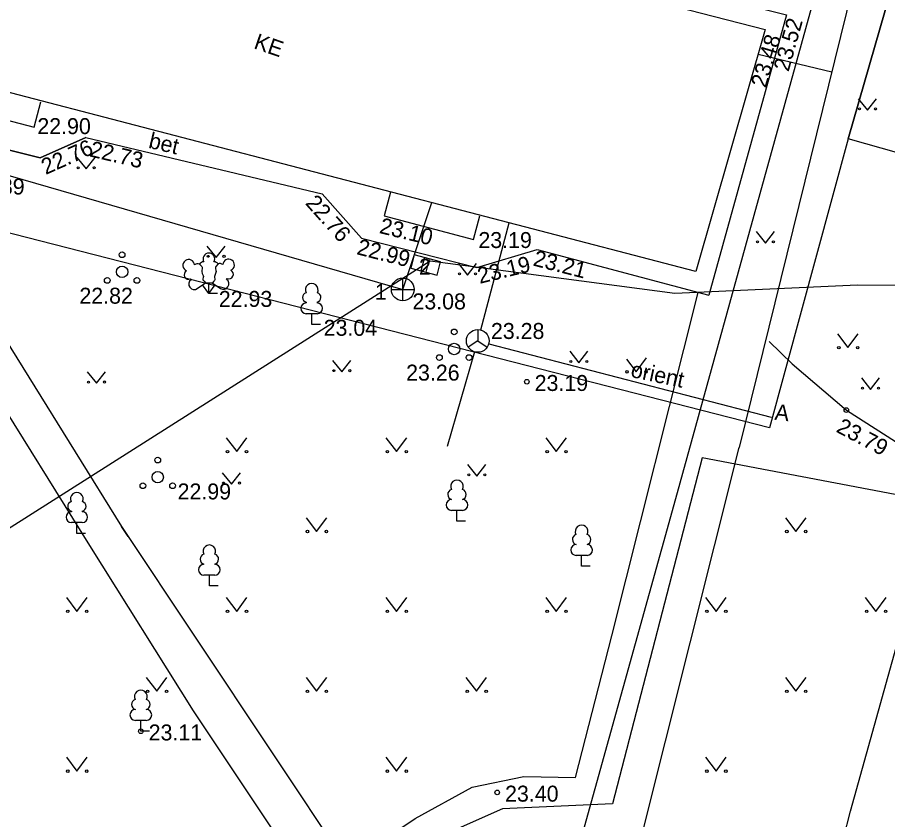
# Model space of a CAD drawing. Extents: x 714391 to 714584, y 6589993 to 6590151.
# Drawn here: x 714490.89 to 714529.01, y 6590039.38 to 6590074.53 of the extents above; entities that cross this region are included whole.
import ezdxf

# ---------------------------------------------------------------- set-up
doc = ezdxf.new("R2010")
doc.units = 0
for name, color, linetype in [('HALJASTUS', 7, 'Continuous'), ('HOONE', 7, 'Continuous'), ('HOONEDET', 7, 'Continuous'), ('KKAEV', 7, 'Continuous'), ('KORGUS', 7, 'Continuous'), ('KTRASS', 7, 'Continuous'), ('MPKAABEL', 7, 'Continuous'), ('POST', 7, 'Continuous'), ('PUU', 7, 'Continuous'), ('SIKAEV', 7, 'Continuous'), ('SITRASS', 7, 'Continuous'), ('SKTRASS', 7, 'Continuous'), ('TEE', 7, 'Continuous'), ('TORU NR', 7, 'Continuous'), ('TTRASS', 7, 'Continuous'), ('По умолчанию', 7, 'Continuous'), ('Слой 1', 7, 'Continuous')]:
    doc.layers.add(name, color=color, linetype=linetype)

msp = doc.modelspace()

# ---------------------------------------------------------------- linework, layer by layer
at = {"layer": 'HALJASTUS'}
for p, q in [((714527.73, 6590070.967), (714528.135, 6590070.462)), ((714528.135, 6590070.462), (714528.53, 6590070.967)), ((714493.503, 6590068.393), (714493.908, 6590067.888)), ((714493.908, 6590067.888), (714494.303, 6590068.393)), ((714523.259, 6590065.142), (714523.664, 6590064.637)), ((714523.664, 6590064.637), (714524.059, 6590065.142)), ((714499.193, 6590064.51), (714499.598, 6590064.005)), ((714499.598, 6590064.005), (714499.993, 6590064.51)), ((714510.21, 6590063.742), (714510.615, 6590063.237)), ((714510.615, 6590063.237), (714511.01, 6590063.742)), ((714526.815, 6590060.664), (714527.278, 6590060.057)), ((714527.278, 6590060.057), (714527.724, 6590060.664)), ((714515.087, 6590059.904), (714515.492, 6590059.399)), ((714515.492, 6590059.399), (714515.887, 6590059.904)), ((714504.701, 6590059.498), (714505.106, 6590058.993)), ((714505.106, 6590058.993), (714505.501, 6590059.498)), ((714493.955, 6590059.001), (714494.36, 6590058.496)), ((714494.36, 6590058.496), (714494.755, 6590059.001)), ((714527.865, 6590058.73), (714528.27, 6590058.225)), ((714528.27, 6590058.225), (714528.665, 6590058.73)), ((714500.037, 6590056.107), (714500.5, 6590055.5)), ((714500.5, 6590055.5), (714500.946, 6590056.107)), ((714507.037, 6590056.107), (714507.5, 6590055.5)), ((714507.5, 6590055.5), (714507.946, 6590056.107)), ((714514.037, 6590056.107), (714514.5, 6590055.5)), ((714514.5, 6590055.5), (714514.946, 6590056.107)), ((714510.616, 6590054.937), (714511.021, 6590054.432)), ((714511.021, 6590054.432), (714511.416, 6590054.937)), ((714499.87, 6590054.576), (714500.275, 6590054.071)), ((714500.275, 6590054.071), (714500.67, 6590054.576)), ((714503.537, 6590052.607), (714504, 6590052)), ((714504, 6590052), (714504.446, 6590052.607)), ((714524.537, 6590052.607), (714525, 6590052)), ((714525, 6590052), (714525.446, 6590052.607)), ((714493.037, 6590049.107), (714493.5, 6590048.5)), ((714493.5, 6590048.5), (714493.946, 6590049.107)), ((714500.037, 6590049.107), (714500.5, 6590048.5)), ((714500.5, 6590048.5), (714500.946, 6590049.107)), ((714507.037, 6590049.107), (714507.5, 6590048.5)), ((714507.5, 6590048.5), (714507.946, 6590049.107)), ((714514.037, 6590049.107), (714514.5, 6590048.5)), ((714514.5, 6590048.5), (714514.946, 6590049.107)), ((714521.037, 6590049.107), (714521.5, 6590048.5)), ((714521.5, 6590048.5), (714521.946, 6590049.107)), ((714528.037, 6590049.107), (714528.5, 6590048.5)), ((714528.5, 6590048.5), (714528.946, 6590049.107)), ((714496.537, 6590045.607), (714497, 6590045)), ((714497, 6590045), (714497.446, 6590045.607)), ((714503.537, 6590045.607), (714504, 6590045)), ((714504, 6590045), (714504.446, 6590045.607)), ((714510.537, 6590045.607), (714511, 6590045)), ((714511, 6590045), (714511.446, 6590045.607)), ((714524.537, 6590045.607), (714525, 6590045)), ((714525, 6590045), (714525.446, 6590045.607)), ((714493.037, 6590042.107), (714493.5, 6590041.5)), ((714493.5, 6590041.5), (714493.946, 6590042.107)), ((714507.037, 6590042.107), (714507.5, 6590041.5)), ((714507.5, 6590041.5), (714507.946, 6590042.107)), ((714521.037, 6590042.107), (714521.5, 6590041.5)), ((714521.5, 6590041.5), (714521.946, 6590042.107))]:
    msp.add_line(p, q, dxfattribs=at)
for centre, radius in [((714527.782, 6590070.517), 0.0428), ((714528.482, 6590070.517), 0.0452), ((714493.555, 6590067.943), 0.0428), ((714494.255, 6590067.943), 0.0452), ((714523.311, 6590064.692), 0.0428), ((714524.011, 6590064.692), 0.0452), ((714495.479, 6590064.13), 0.125), ((714499.245, 6590064.06), 0.0428), ((714499.945, 6590064.06), 0.0452), ((714495.479, 6590063.38), 0.25), ((714494.829, 6590063.005), 0.125), ((714496.129, 6590063.005), 0.125), ((714510.262, 6590063.292), 0.0428), ((714510.962, 6590063.292), 0.0452), ((714510.029, 6590060.747), 0.125), ((714510.029, 6590059.997), 0.25), ((714526.877, 6590060.057), 0.055), ((714527.706, 6590060.057), 0.055), ((714509.379, 6590059.622), 0.125), ((714510.679, 6590059.622), 0.125), ((714515.139, 6590059.454), 0.0428), ((714515.839, 6590059.454), 0.0452), ((714504.753, 6590059.048), 0.0428), ((714505.453, 6590059.048), 0.0452), ((714494.007, 6590058.551), 0.0428), ((714494.707, 6590058.551), 0.0452), ((714527.917, 6590058.28), 0.0428), ((714528.617, 6590058.28), 0.0452), ((714500.099, 6590055.5), 0.055), ((714500.928, 6590055.5), 0.055), ((714507.099, 6590055.5), 0.055), ((714507.928, 6590055.5), 0.055), ((714514.099, 6590055.5), 0.055), ((714514.928, 6590055.5), 0.055), ((714497.04, 6590055.131), 0.125), ((714497.04, 6590054.381), 0.25), ((714510.668, 6590054.488), 0.0428), ((714511.368, 6590054.488), 0.0452), ((714496.39, 6590054.006), 0.125), ((714497.69, 6590054.006), 0.125), ((714499.922, 6590054.126), 0.0428), ((714500.622, 6590054.126), 0.0452), ((714503.599, 6590052), 0.055), ((714504.428, 6590052), 0.055), ((714524.599, 6590052), 0.055), ((714525.428, 6590052), 0.055), ((714493.099, 6590048.5), 0.055), ((714493.928, 6590048.5), 0.055), ((714500.099, 6590048.5), 0.055), ((714500.928, 6590048.5), 0.055), ((714507.099, 6590048.5), 0.055), ((714507.928, 6590048.5), 0.055), ((714514.099, 6590048.5), 0.055), ((714514.928, 6590048.5), 0.055), ((714521.099, 6590048.5), 0.055), ((714521.928, 6590048.5), 0.055), ((714528.099, 6590048.5), 0.055), ((714528.928, 6590048.5), 0.055), ((714496.599, 6590045), 0.055), ((714497.428, 6590045), 0.055), ((714503.599, 6590045), 0.055), ((714504.428, 6590045), 0.055), ((714510.599, 6590045), 0.055), ((714511.428, 6590045), 0.055), ((714524.599, 6590045), 0.055), ((714525.428, 6590045), 0.055), ((714493.099, 6590041.5), 0.055), ((714493.928, 6590041.5), 0.055), ((714507.099, 6590041.5), 0.055), ((714507.928, 6590041.5), 0.055), ((714521.099, 6590041.5), 0.055), ((714521.928, 6590041.5), 0.055)]:
    msp.add_circle(centre, radius, dxfattribs=at)
at = {"layer": 'HOONE'}
for points in [[(714520.618, 6590063.399), (714481.385, 6590073.617), (714484.074, 6590084.17), (714523.648, 6590073.994), (714520.618, 6590063.399)], [(714487.937, 6590071.893), (714487.647, 6590070.755), (714491.627, 6590069.716), (714491.916, 6590070.835)], [(714507.236, 6590066.871), (714506.966, 6590065.84), (714510.869, 6590064.791), (714511.151, 6590065.835)]]:
    msp.add_lwpolyline(points, dxfattribs=at)
at = {"layer": 'KKAEV'}
for p, q in [((714507.775, 6590062.109), (714507.775, 6590063.109)), ((714507.275, 6590062.609), (714508.275, 6590062.609))]:
    msp.add_line(p, q, dxfattribs=at)
msp.add_circle((714507.775, 6590062.609), 0.5, dxfattribs=at)
at = {"layer": 'KORGUS'}
for centre in [(714513.21, 6590058.564), (714527.207, 6590057.322), (714496.3, 6590043.248), (714511.913, 6590040.568)]:
    msp.add_circle(centre, 0.1, dxfattribs=at)
at = {"layer": 'KTRASS'}
for p, q in [((714488.663, 6590068.145), (714507.775, 6590062.609)), ((714507.775, 6590062.609), (714509.052, 6590066.411))]:
    msp.add_line(p, q, dxfattribs=at)
at = {"layer": 'MPKAABEL'}
msp.add_lwpolyline([(714558.719, 6590063.793), (714557.614, 6590062.993), (714553.32, 6590062.662), (714527.694, 6590062.802), (714519.691, 6590062.433), (714508.979, 6590063.853), (714473.93, 6590041.599)], dxfattribs=at)
at = {"layer": 'POST'}
for p, q in [((714508.281, 6590064.124), (714508.127, 6590063.547)), ((714509.435, 6590063.816), (714508.281, 6590064.124)), ((714508.727, 6590064.005), (714508.573, 6590063.428)), ((714508.937, 6590063.949), (714508.783, 6590063.372)), ((714508.127, 6590063.547), (714509.282, 6590063.24)), ((714509.282, 6590063.24), (714509.435, 6590063.816))]:
    msp.add_line(p, q, dxfattribs=at)
at = {"layer": 'PUU'}
for p, q in [((714498.498, 6590063.031), (714498.473, 6590063.066)), ((714498.773, 6590062.646), (714499.133, 6590062.901)), ((714499.283, 6590062.426), (714499.008, 6590062.811)), ((714499.133, 6590062.901), (714499.428, 6590062.901)), ((714499.283, 6590062.426), (714499.283, 6590062.901)), ((714499.283, 6590062.426), (714499.553, 6590062.816)), ((714499.428, 6590062.901), (714499.788, 6590062.656)), ((714500.058, 6590063.046), (714500.078, 6590063.081)), ((714499.663, 6590062.426), (714499.283, 6590062.426)), ((714503.547, 6590062.049), (714503.547, 6590062.019)), ((714504.027, 6590062.049), (714504.027, 6590062.019)), ((714504.027, 6590061.544), (714503.547, 6590061.544)), ((714503.787, 6590061.069), (714503.787, 6590061.544)), ((714504.167, 6590061.069), (714503.787, 6590061.069)), ((714493.257, 6590052.896), (714493.257, 6590052.866)), ((714493.737, 6590052.896), (714493.737, 6590052.866)), ((714510.389, 6590052.926), (714509.909, 6590052.926)), ((714510.149, 6590052.451), (714510.149, 6590052.926)), ((714510.529, 6590052.451), (714510.149, 6590052.451)), ((714493.737, 6590052.391), (714493.257, 6590052.391)), ((714493.497, 6590051.916), (714493.497, 6590052.391)), ((714493.877, 6590051.916), (714493.497, 6590051.916)), ((714515.849, 6590050.954), (714515.369, 6590050.954)), ((714515.609, 6590050.479), (714515.609, 6590050.954)), ((714515.989, 6590050.479), (714515.609, 6590050.479)), ((714499.543, 6590050.088), (714499.063, 6590050.088)), ((714499.303, 6590049.613), (714499.303, 6590050.088)), ((714499.683, 6590049.613), (714499.303, 6590049.613)), ((714496.54, 6590043.723), (714496.06, 6590043.723)), ((714496.3, 6590043.248), (714496.3, 6590043.723)), ((714496.68, 6590043.248), (714496.3, 6590043.248))]:
    msp.add_line(p, q, dxfattribs=at)
for points in [[(714498.868, 6590063.711), (714498.973, 6590063.611), (714498.988, 6590063.581), (714498.988, 6590063.526), (714498.973, 6590063.436), (714498.973, 6590063.391), (714498.993, 6590063.311), (714499.033, 6590063.221), (714499.043, 6590063.176), (714499.038, 6590063.131), (714499.023, 6590063.066), (714499.023, 6590063.036), (714499.043, 6590062.996), (714499.068, 6590062.966), (714499.133, 6590062.901)], [(714499.688, 6590063.726), (714499.593, 6590063.611), (714499.578, 6590063.581), (714499.578, 6590063.526), (714499.593, 6590063.436), (714499.598, 6590063.391), (714499.578, 6590063.311), (714499.538, 6590063.221), (714499.528, 6590063.176), (714499.533, 6590063.131), (714499.548, 6590063.066), (714499.548, 6590063.036), (714499.528, 6590062.996), (714499.503, 6590062.966), (714499.433, 6590062.901)]]:
    msp.add_lwpolyline(points, dxfattribs=at)
for centre, radius, start, end in [((714498.4, 6590063.663), 0.256, 4.5218, 125.5364), ((714499.283, 6590063.946), 0.256, 90.0013, 211.0159), ((714499.283, 6590063.946), 0.256, 328.9841, 89.9987), ((714500.143, 6590063.679), 0.256, 55.522, 176.5367), ((714500.143, 6590063.679), 0.256, 294.5049, 55.5195), ((714498.4, 6590063.663), 0.256, 125.5389, 246.5536), ((714498.786, 6590063.53), 0.202, 65.2382, 130.7412), ((714499.045, 6590063.613), 0.202, 84.7965, 150.2995), ((714499.52, 6590063.613), 0.202, 34.3857, 95.2035), ((714499.759, 6590063.539), 0.202, 50.3173, 111.1351), ((714498.4, 6590063.254), 0.202, 120.3342, 291.9047), ((714500.151, 6590063.27), 0.202, 249.1538, 60.7243), ((714498.637, 6590062.84), 0.237, 125.5377, 305.5366), ((714499.921, 6590062.852), 0.237, 235.5219, 55.5208), ((714503.787, 6590062.589), 0.277, 332.5799, 207.4201), ((714503.597, 6590062.257), 0.212, 105.2441, 257.079), ((714503.977, 6590062.257), 0.212, 282.921, 74.7559), ((714503.549, 6590061.781), 0.237, 90, 270), ((714504.024, 6590061.781), 0.237, 270, 90), ((714510.149, 6590053.971), 0.277, 332.5799, 207.4201), ((714493.497, 6590053.436), 0.277, 332.5799, 207.4201), ((714509.979, 6590053.624), 0.233, 109.0217, 253.1415), ((714510.319, 6590053.624), 0.233, 286.8508, 70.9859), ((714493.307, 6590053.104), 0.212, 105.2441, 257.079), ((714493.687, 6590053.104), 0.212, 282.921, 74.7559), ((714509.912, 6590053.163), 0.238, 90.0016, 269.3953), ((714510.386, 6590053.163), 0.238, 270.6047, 89.9984), ((714493.259, 6590052.629), 0.237, 90, 270), ((714493.734, 6590052.629), 0.237, 270, 90), ((714515.609, 6590051.999), 0.277, 332.5799, 207.4201), ((714515.439, 6590051.652), 0.233, 109.0217, 253.1415), ((714515.779, 6590051.652), 0.233, 286.8508, 70.9859), ((714499.303, 6590051.133), 0.277, 332.5799, 207.4201), ((714515.372, 6590051.191), 0.238, 90.0016, 269.3953), ((714515.846, 6590051.191), 0.238, 270.6047, 89.9984), ((714499.133, 6590050.786), 0.233, 109.0217, 253.1415), ((714499.473, 6590050.786), 0.233, 286.8508, 70.9859), ((714499.066, 6590050.325), 0.238, 90.0016, 269.3953), ((714499.54, 6590050.325), 0.238, 270.6047, 89.9984), ((714496.3, 6590044.768), 0.277, 332.5799, 207.4201), ((714496.13, 6590044.421), 0.233, 109.0217, 253.1415), ((714496.47, 6590044.421), 0.233, 286.8508, 70.9859), ((714496.063, 6590043.96), 0.238, 90.0016, 269.3953), ((714496.537, 6590043.96), 0.238, 270.6047, 89.9984)]:
    msp.add_arc(centre, radius, start, end, dxfattribs=at)
at = {"layer": 'SIKAEV'}
for p, q in [((714511.061, 6590060.854), (714511.061, 6590060.354)), ((714511.061, 6590060.354), (714510.646, 6590060.079)), ((714511.061, 6590060.354), (714511.476, 6590060.079))]:
    msp.add_line(p, q, dxfattribs=at)
msp.add_circle((714511.061, 6590060.354), 0.5, dxfattribs=at)
at = {"layer": 'SITRASS'}
for p, q in [((714511.19, 6590060.837), (714512.44, 6590065.529)), ((714511.545, 6590060.228), (714523.916, 6590057.008)), ((714510.922, 6590059.874), (714509.721, 6590055.727))]:
    msp.add_line(p, q, dxfattribs=at)
at = {"layer": 'SKTRASS'}
msp.add_lwpolyline([(714531.495, 6590096.001), (714522.972, 6590065.168), (714519.718, 6590053.426), (714509.807, 6590017.772), (714505.951, 6590002.864)], dxfattribs=at)
at = {"layer": 'TEE'}
for points in [[(714492.924, 6590082.556), (714483.739, 6590085.22), (714483.316, 6590084.953), (714480.306, 6590072.893), (714485.078, 6590071.74), (714486.316, 6590069.766), (714491.895, 6590068.37), (714493.892, 6590069.273), (714504.243, 6590066.794), (714505.962, 6590064.851), (714511.02, 6590063.567), (714513.67, 6590064.358), (714521.189, 6590062.359)], [(714515.124, 6590077.012), (714524.589, 6590074.649), (714521.189, 6590062.359)], [(714493.892, 6590069.273), (714491.895, 6590068.37), (714486.316, 6590069.766), (714485.078, 6590071.74)], [(714503.783, 6590036.391), (714498.601, 6590044.145), (714494.073, 6590051.394), (714489.657, 6590058.462), (714484.091, 6590067.913), (714485.295, 6590068.584), (714495.449, 6590052.222), (714495.743, 6590051.781), (714495.449, 6590052.222), (714505.314, 6590037.415)], [(714505.962, 6590064.851), (714504.243, 6590066.794)], [(714470.452, 6590014.088), (714483.473, 6590022.62), (714491.732, 6590028.328), (714508.314, 6590039.422), (714510.811, 6590040.796), (714513.08, 6590041.27), (714515.342, 6590041.216), (714516.939, 6590047.426), (714520.722, 6590062.481)], [(714523.83, 6590060.323), (714524.838, 6590059.346), (714527.207, 6590057.322), (714530.612, 6590055.143), (714533.466, 6590053.803), (714539.862, 6590051.373), (714544.939, 6590049.949), (714549.327, 6590048.405), (714554.662, 6590046.175), (714555.973, 6590045.43), (714557.565, 6590044.068), (714560.558, 6590042.157), (714562.991, 6590040.414), (714566.112, 6590037.695), (714570.003, 6590051.519), (714571.762, 6590062.449)], [(714525.477, 6590005.373), (714525.684, 6590006.074), (714527.69, 6590005.573), (714531.538, 6590012.432), (714532.385, 6590015.369), (714531.445, 6590019.084), (714529.795, 6590023.709), (714527.067, 6590029.841), (714526.32, 6590032.242), (714526.158, 6590034.948), (714527.384, 6590039.748), (714530.089, 6590049.424), (714531.112, 6590053.289), (714520.888, 6590055.232), (714516.962, 6590040.074), (714512.15, 6590039.854), (714507.831, 6590037.94), (714505.233, 6590035.896), (714491.681, 6590027.029), (714484.169, 6590021.661), (714470.258, 6590012.413)]]:
    msp.add_lwpolyline(points, dxfattribs=at)
at = {"layer": 'TTRASS'}
msp.add_line((714526.578, 6590072.128), (714523.338, 6590072.908), dxfattribs=at)
msp.add_lwpolyline([(714510.928, 6590008.703), (714512.829, 6590017.079), (714522.511, 6590055.684), (714522.522, 6590055.681), (714534.537, 6590104.393)], dxfattribs=at)
at = {"layer": 'По умолчанию'}
for p, q in [((714517.575, 6590059.557), (714518, 6590059)), ((714518, 6590059), (714518.446, 6590059.607))]:
    msp.add_line(p, q, dxfattribs=at)
for centre in [(714517.599, 6590059), (714518.428, 6590059)]:
    msp.add_circle(centre, 0.055, dxfattribs=at)
at = {"layer": 'Слой 1'}
for points in [[(714478.99, 6590085.97), (714532.4, 6590086.95), (714527.28, 6590069.21), (714523.84, 6590056.54), (714478.28, 6590068.22)], [(714579.84, 6590087.07), (714574.08, 6590064.07), (714572.19, 6590056.5), (714562.09, 6590059.36), (714527.28, 6590069.21), (714532.4, 6590086.95)]]:
    msp.add_lwpolyline(points, close=True, dxfattribs=at)

# ---------------------------------------------------------------- texts
at = {"layer": 'HOONE'}
msp.add_text('KE', height=0.7, rotation=341.0277, dxfattribs=at).set_placement((714501.208, 6590073.182))
at = {"layer": 'HOONEDET'}
msp.add_text('bet', height=0.7, rotation=346.6797, dxfattribs=at).set_placement((714496.601, 6590068.821))
at = {"layer": 'KORGUS'}
for s, rotation, p in [('23.52', 74.3688, (714524.675, 6590072.122)), ('23.48', 73.3891, (714523.679, 6590071.407)), ('22.76', 23.8988, (714492.134, 6590067.623)), ('22.73', 346.7316, (714494.021, 6590068.444)), ('22.76', 311.7459, (714503.476, 6590066.368)), ('23.10', 346.4191, (714506.715, 6590065.085)), ('22.99', 345.6255, (714505.72, 6590064.158)), ('23.21', 345.6832, (714513.444, 6590063.662)), ('23.19', 13.707, (714511.147, 6590062.852)), ('23.79', 332.1627, (714526.719, 6590056.386))]:
    msp.add_text(s, height=0.7, rotation=rotation, dxfattribs=at).set_placement(p)
for s, p in [('22.90', (714491.767, 6590069.415)), ('22.89', (714488.867, 6590066.767)), ('23.19', (714511.088, 6590064.423)), ('22.82', (714493.609, 6590061.984)), ('22.93', (714499.716, 6590061.843)), ('23.08', (714508.199, 6590061.735)), ('23.04', (714504.31, 6590060.577)), ('23.28', (714511.638, 6590060.438)), ('23.26', (714507.922, 6590058.613)), ('23.19', (714513.553, 6590058.159)), ('22.99', (714497.91, 6590053.406)), ('23.11', (714496.643, 6590042.844)), ('23.40', (714512.257, 6590040.163))]:
    msp.add_text(s, height=0.7, dxfattribs=at).set_placement(p)
at = {"layer": 'SITRASS'}
msp.add_text('orient', height=0.7, rotation=348.0701, dxfattribs=at).set_placement((714517.723, 6590058.778))
at = {"layer": 'TEE'}
msp.add_text('A', height=0.7, rotation=353.6135, dxfattribs=at).set_placement((714524.045, 6590056.9))
at = {"layer": 'TORU NR'}
for s, p in [('2', (714508.485, 6590063.254)), ('1', (714506.552, 6590062.158))]:
    msp.add_text(s, height=0.7, dxfattribs=at).set_placement(p)

doc.saveas('drawing.dxf')
